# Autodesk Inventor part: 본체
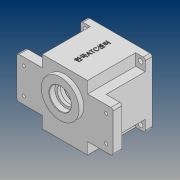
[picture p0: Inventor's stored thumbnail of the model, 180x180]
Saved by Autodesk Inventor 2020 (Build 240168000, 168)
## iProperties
Created: 2020-07
Part Number: 본체
Material: 일반
Document SubType Name: Modeling
Designer: PC312-
Density: 1 g/cm^3
Appearance: 기본값
Author: PC312-
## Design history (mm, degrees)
sketch "스케치2"
  geometry: L1 (-47, 47)-(47, 47); L2 (47, 47)-(47, -47); L3 (47, -47)-(-47, -47); L4 (-47, -47)-(-47, 47); L5 (-47, 47)-(47, -47); L6 (47, 47)-(-47, -47); 1 further point
  constraints: 12 end point, 2 midpoint, 2 parallel, 1 horizontal, 1 perpendicular
  dimensions: "d0" = 94 distance of L2.end L3.end; "d1" = 94 distance of L1.end L2.end
extrude "돌출1" new body sketch "스케치2" stored distance "d2" = 80; taper "d3" = 0 deg
sketch "스케치3"
  geometry: L1 (-70, 30)-(70, 30); L2 (70, 30)-(70, -30); L3 (70, -30)-(-70, -30); L4 (-70, -30)-(-70, 30); L5 (-70, 30)-(70, -30); L6 (70, 30)-(-70, -30); 1 further point
  constraints: 12 end point, 2 midpoint, 2 parallel, 1 horizontal, 1 perpendicular
  dimensions: "d4" = 140 distance of L2.end L3.end; "d5" = 60 distance of L1.end L2.end
extrude "돌출2" join sketch "스케치3" distance "d6" = 13; taper "d7" = 0 deg
sketch "스케치4"
  geometry: L1 (47, 47)-(-47, 47) reference; L2 (33, 47)-(33, 30); L3 (33, 30)-(49.544, 30); L4 (70, 30)-(47, 30) reference; L5 (47, 30)-(47, 47) reference; L6 (-47, -47)-(-47, 47) reference; L7 (-47, 30)-(-33, 30); L8 (-33, 47)-(-33, 30); 2 further points
  constraints: 8 end point, 4 point on line, 2 vertical, 1 horizontal
  dimensions: "d8" = 33 distance from line of L2 point (0, 0); "d9" = 30 distance from line of point (0, 0) L3; "d12" = 33 distance from line of L8 point (0, 0); "d13" = 30 distance from line of point (0, 0) L7
extrude "돌출3" cut sketch "스케치4" distance "d10" = 70; taper "d11" = 0 deg
sketch "스케치5"
  geometry: C1 r 43 at (0, 0); C2 r 40 at (0, 0); 1 further point
  constraints: 2 centre point, 2 coincident
  dimensions: "d20" = 86 diameter of C1; "d21" = 80 diameter of C2
extrude "돌출4" cut sketch "스케치5" distance "d22" = 9; taper "d23" = 0 deg
extrude "돌출5" cut sketch "스케치5" distance "d24" = 71; taper "d25" = 0 deg
sketch "스케치6"
  geometry: A1 r 21 centre (0, 11) between (8.978, -7.984) and (-8.978, -7.984); A2 r 15 centre (0, -20) between (-8.978, -7.984) and (8.978, -7.984); 1 further point
  constraints: 4 point on circle, 2 centre point, 2 vertical alignment
  dimensions: "d26" = 42 diameter of A1; "d27" = 30 diameter of A2; "d28" = 11 distance of point (0, 0) A1.centre; "d29" = 20 distance of A2.centre point (0, 0)
extrude "돌출6" join sketch "스케치6" distance "d30" = 7; taper "d31" = 0 deg
sketch "스케치7"
  geometry: C1 r 17.5 at (0, 11); C2 r 11 at (0, -20); C3 r 12.5 at (0, 11); C4 r 9.5 at (0, -20); A1 r 21 centre (0, 11) between (8.978, -7.984) and (-8.978, -7.984) reference; A2 r 15 centre (0, -20) between (-8.978, -7.984) and (8.978, -7.984) reference; 1 further point
  constraints: 4 centre point, 4 coincident
  dimensions: "d32" = 35 diameter of C1; "d33" = 22 diameter of C2; "d34" = 25 diameter of C3; "d35" = 19 diameter of C4
extrude "돌출7" cut sketch "스케치7" distance "d36" = 10; taper "d37" = 0 deg
extrude "돌출8" cut sketch "스케치7" distance "d38" = 14.7; taper "d39" = 0 deg
extrude "돌출11" cut sketch "스케치7" distance "d44" = 7; taper "d45" = 0 deg
extrude "돌출12" cut sketch "스케치7" distance "d46" = 10; taper "d47" = 0 deg
sketch "스케치8"
  geometry: C1 r 27.5 at (0, 11); 1 further point
  constraints: 1 centre point, 1 vertical alignment
  dimensions: "d48" = 55 diameter of C1; "d49" = 11 distance of point (0, 0) C1.centre
extrude "돌출13" join sketch "스케치8" distance "d50" = 7; taper "d51" = 0 deg
sketch "스케치9"
  geometry: C1 r 27.5 at (0, 0) reference; C2 r 16 at (0, 0); 1 further point
  constraints: 1 centre point, 1 coincident
  dimensions: "d52" = 32 diameter of C2
extrude "돌출14" cut sketch "스케치9" distance "d53" = 8.3; taper "d54" = 0 deg
sketch "스케치10"
  geometry: A1 r 4 centre (-36, 0) between (-36.19, -3.995) and (-36.19, 3.995); A2 r 3 centre (-36.333, 6.992) between (-39.279, 7.559) and (-36.19, 3.995); A3 r 3 centre (-36.333, -6.992) between (-36.19, -3.995) and (-39.279, -7.559); A4 r 40 centre (0, 0) between (-39.279, 7.559) and (-39.279, -7.559) reference; 1 further point
  constraints: 8 point on circle, 4 tangent, 3 centre point, 1 horizontal alignment
  dimensions: "d55" = 8 diameter of A1; "d56" = 36 distance of point (0, 0) A1.centre; "d57" = 6 diameter of A2; "d58" = 6 diameter of A3
extrude "돌출15" join sketch "스케치10" distance "d59" = 62; taper "d60" = 0 deg
sketch "스케치11"
  geometry: C1 r 3.5 at (-40, 40); 1 further point
  constraints: 1 centre point
  dimensions: "d61" = 7 diameter of C1; "d62" = 40 horizontal distance of C1.centre point (0, 0); "d63" = 40 horizontal distance of C1.centre point (0, 0)
extrude "돌출16" cut sketch "스케치11" extent not by distance; stored distance "d64" = 0; taper "d65" = 0 deg
sketch "스케치12"
  geometry: 2 further points
  dimensions: "d72" = 60 horizontal distance of point (-60, 19) point (0, 0); "d73" = 19 vertical distance of point (-60, 19) point (0, 0)
hole "구멍1" sketch "스케치12" at (-60, 19) diameter "d74" = 4.5; stored, may be unused: countersink angle "d78" = 90 deg, drill point angle "d80" = 118 deg; dims "d75" = 7, "d76" = 10, "d77" = 5, "d79" = 9
sketch "스케치13"
  geometry: A1 r 4 centre (-36, 0) between (-36.19, -3.995) and (-36.19, 3.995) reference; 2 further points
  constraints: 1 coincident
hole "구멍2" sketch "스케치13" at (-36, 0) diameter "d87" = 3.242; stored, may be unused: countersink angle "d91" = 90 deg, drill point angle "d93" = 118 deg; dims "d88" = 7, "d89" = 10, "d90" = 5, "d92" = 9
node "작업 평면1"
sketch "스케치15"
  geometry: L1 (0, 0)-(94, 0) reference; 2 further points
  constraints: 1 coincident, 1 other
  dimensions: "d95" = 40 distance from line of L1 point (47, -40)
feature "엠보싱1" sketch "스케치15" dims "d8" = 33, "d9" = 30, "d96" = 0.5, "d97" = 0
chamfer "모따기2" distance "d101" = 1; stored, may be unused: second distance "d102" = 2, angle "d103" = 30 deg
chamfer "모따기3" distance "d104" = 1; stored, may be unused: second distance "d105" = 2, angle "d106" = 30 deg
fillet "모깎기1" dims "d107" = 3
fillet "모깎기2" dims "d108" = 3
fillet "모깎기3" dims "d109" = 3
chamfer "모따기4" distance "d110" = 0.8; stored, may be unused: second distance "d111" = 2, angle "d112" = 30 deg
node "솔리드1"
pattern_linear "직사각형 패턴1" dims "d16" = 80, "d19" = 77
mirror "미러1"
pattern_linear "직사각형 패턴2" dims "d68" = 80, "d71" = 80
pattern_linear "직사각형 패턴3" dims "d83" = 120, "d86" = 38
mirror "미러2"
feature "A9D066F2-1C7D-4E18-AEED-F7BC21143FA4" dims "d74" = 4.5, "d75" = 7, "d76" = 10, "d77" = 5, "d78" = 90 deg, "d79" = 9, "d80" = 118 deg
other parameters: "d94" = 0.5
